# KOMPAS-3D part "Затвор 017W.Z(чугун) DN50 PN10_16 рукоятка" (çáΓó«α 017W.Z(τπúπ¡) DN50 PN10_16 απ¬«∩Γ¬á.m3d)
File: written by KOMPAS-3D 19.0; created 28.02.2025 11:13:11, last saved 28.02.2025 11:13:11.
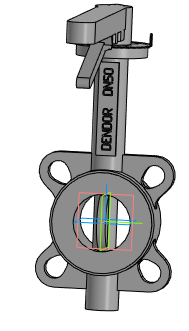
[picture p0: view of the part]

Document properties: Автор: Евгений; Полное имя файла: Затвор 017W.Z(чугун) DN50 PN10_16 рукоятка.a3d

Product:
- Part/product: Затвор 017W.Z(чугун) DN50 PN10_16 рукоятка
    Масса: 4.51107

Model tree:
1. Операция без истории:1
